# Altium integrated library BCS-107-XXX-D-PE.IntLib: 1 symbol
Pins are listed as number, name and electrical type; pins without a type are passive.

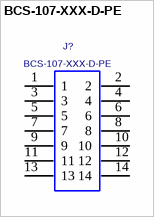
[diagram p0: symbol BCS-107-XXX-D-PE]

## BCS-107-XXX-D-PE
designator J?
BOX CONNECTOR DOUBLE ROW SOCKET STRIP,PASS-THROUGH ENTRY.; MANUFACTURER: SAMTEC
footprint BCS-107-XXX-D-PE
pins: 1, 2, 3, 4, 5, 6, 7, 8, 9, 10, 11, 12, 13, 14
